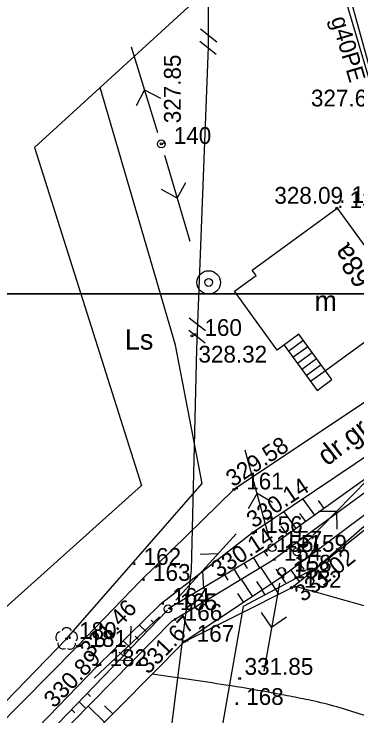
# Model space of a CAD drawing. Extents: x 4632591 to 4653165, y 5351032 to 5369868.
# Drawn here: x 4644663.8 to 4644694.4, y 5358462.3 to 5358525 of the extents above; entities that cross this region are included whole.
import ezdxf

# ---------------------------------------------------------------- set-up
doc = ezdxf.new("R2010")
doc.units = 0
for name, color, linetype in [('EADPD_238', 7, 'Continuous'), ('EBTPO_352', 7, 'Continuous'), ('EBUPP_312', 7, 'Continuous'), ('EDZPX_299', 7, 'Continuous'), ('EKLPK_217', 7, 'Continuous'), ('EUZPU_424', 7, 'Continuous'), ('SZZPZ_922', 7, 'Continuous'), ('UEEPA_510', 7, 'Continuous'), ('UEETA_516', 7, 'Continuous'), ('UGGPO_553', 7, 'Continuous'), ('UTTTA_521', 7, 'Continuous'), ('UWWPA_907', 7, 'Continuous'), ('Warstwa 40', 7, 'Continuous'), ('Warstwa 60', 7, 'Continuous'), ('Warstwa 62', 7, 'Continuous'), ('WUKPS_403', 7, 'Continuous'), ('WUKPS_820', 7, 'Continuous'), ('WUKPS_823', 7, 'Continuous'), ('WUKPS_824', 7, 'Continuous'), ('WWRPH_811', 7, 'Continuous')]:
    doc.layers.add(name, color=color, linetype=linetype)

msp = doc.modelspace()

# ---------------------------------------------------------------- linework, layer by layer
at = {"layer": 'EBTPO_352'}
for p, q in [((4644688.332, 5358494.893), (4644689.655, 5358495.855)), ((4644688.727, 5358494.350000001), (4644690.05, 5358495.312)), ((4644689.122, 5358493.807), (4644690.445, 5358494.769)), ((4644689.517, 5358493.264), (4644690.84, 5358494.226)), ((4644689.9120000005, 5358492.721), (4644691.235, 5358493.683)), ((4644691.63, 5358493.14), (4644690.307, 5358492.178))]:
    msp.add_line(p, q, dxfattribs=at)
msp.add_lwpolyline([(4644687.937, 5358495.437), (4644690.883, 5358491.386), (4644692.206, 5358492.348), (4644691.63, 5358493.14)], dxfattribs=at)
at = {"layer": 'EBUPP_312'}
msp.add_lwpolyline([(4644689.26, 5358496.399), (4644687.319, 5358494.987), (4644683.495, 5358500.243), (4644685.436, 5358501.655), (4644685.083, 5358502.14), (4644692.68, 5358507.67), (4644699.232, 5358498.669), (4644691.63, 5358493.14)], close=True, dxfattribs=at)
at = {"layer": 'EDZPX_299'}
for p, q in [((4644681.918138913, 5358522.506503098), (4644680.461517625, 5358523.663332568)), ((4644681.875868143, 5358521.407315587), (4644680.419246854, 5358522.5641450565)), ((4644680.9253407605, 5358496.690287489), (4644679.468719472, 5358497.847116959)), ((4644680.88306999, 5358495.591099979), (4644679.426448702, 5358496.747929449))]:
    msp.add_line(p, q, dxfattribs=at)
at = {"layer": 'EKLPK_217'}
msp.add_lwpolyline([(4644589.437877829, 5358446.057148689), (4644590.15, 5358443.3), (4644594.36, 5358439.41), (4644607.9, 5358437.69), (4644615.73, 5358442.350000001), (4644623.29, 5358443.5), (4644627.91, 5358442.78), (4644641.76, 5358446.850000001), (4644656.67, 5358456.98), (4644668.51, 5358469.17), (4644674.28, 5358475.79), (4644680.614947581, 5358483.058172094), (4644678.245093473, 5358495.410952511), (4644671.512576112, 5358518.445863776)], dxfattribs=at)
at = {"layer": 'EUZPU_424'}
for points in [[(4644736.519549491, 5358573.425323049), (4644734.7336056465, 5358569.580341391), (4644733.014156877, 5358558.486645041), (4644724.43, 5358530.37), (4644718.67, 5358515.99), (4644711.55, 5358501.11), (4644708.07, 5358496.17), (4644703.46, 5358490.97), (4644685.13, 5358478.64), (4644676.84, 5358472.22), (4644671.23, 5358466.74), (4644658.94, 5358454.03), (4644646.98, 5358446.3100000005), (4644643, 5358444.41)], [(4644729.51, 5358555.12), (4644722.11, 5358531.42), (4644716.49, 5358516.97), (4644709.43, 5358502.48), (4644706.3100000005, 5358497.61), (4644701.62, 5358493.26), (4644695.2079700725, 5358490.354165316), (4644683.44, 5358482.53), (4644675.12, 5358474.36), (4644669.43, 5358468.46), (4644657.26, 5358456.17), (4644645.62, 5358448.34)]]:
    msp.add_lwpolyline(points, dxfattribs=at)
at = {"layer": 'SZZPZ_922'}
msp.add_circle((4644668.51, 5358469.17), 0.09, dxfattribs=at)
for centre, start, end in [((4644668.517, 5358469.67), 30.769569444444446, 149.23063055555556), ((4644668.041, 5358469.322), 103.05194166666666, 221.33515277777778), ((4644668.992000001, 5358469.3270000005), 318.9390055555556, 77.55512500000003), ((4644668.218, 5358468.769), 174.17266944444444, 292.6156638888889), ((4644668.806, 5358468.762), 246.13102500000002, 4.522500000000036)]:
    msp.add_arc(centre, 0.5, start, end, dxfattribs=at)
at = {"layer": 'UEEPA_510'}
for centre in [(4644676.97, 5358513.41), (4644686.87, 5358477.32), (4644689.09, 5358476.96), (4644687.72, 5358475.19), (4644677.569690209, 5358471.853793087)]:
    msp.add_circle(centre, 0.35000000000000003, dxfattribs=at)
at = {"layer": 'UEETA_516'}
for p, q in [((4644676.659732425, 5358514.413112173), (4644674.295788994, 5358522.055871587)), ((4644675.47776071, 5358518.234491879), (4644674.7314681, 5358516.819794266)), ((4644675.47776071, 5358518.234491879), (4644676.892458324, 5358517.48819927)), ((4644677.26731119, 5358512.402971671), (4644679.53253931, 5358504.730374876)), ((4644678.399925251, 5358508.566673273), (4644679.164391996, 5358509.97163327)), ((4644678.399925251, 5358508.566673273), (4644676.994965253, 5358509.331140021)), ((4644686.588960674, 5358478.331690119), (4644684.447708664, 5358486.039805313)), ((4644689.82446119, 5358477.710377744), (4644695.420355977, 5358483.427541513)), ((4644685.518334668, 5358482.185747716), (4644684.7313193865, 5358480.793293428)), ((4644685.518334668, 5358482.185747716), (4644686.910788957, 5358481.398732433)), ((4644692.622408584, 5358480.568959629), (4644691.02302493, 5358480.551815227)), ((4644692.622408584, 5358480.568959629), (4644692.639552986, 5358478.969575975)), ((4644687.534542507, 5358474.156508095), (4644686.121533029, 5358466.282284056)), ((4644686.828037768, 5358470.219396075), (4644685.914583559, 5358471.532378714)), ((4644686.828037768, 5358470.219396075), (4644688.141020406, 5358471.132850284))]:
    msp.add_line(p, q, dxfattribs=at)
at = {"layer": 'UGGPO_553'}
for points in [[(4644690.36324522, 5358535.7036739), (4644691.579033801, 5358532.559831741), (4644696.43465227, 5358516.11393335), (4644701.2098301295, 5358500.333543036)], [(4644681.162880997, 5358527.280149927), (4644681.159171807, 5358525.742968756), (4644681.150276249, 5358522.056427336), (4644680.112786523, 5358495.078074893), (4644679.631088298, 5358475.317567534), (4644676.611747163, 5358451.335490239), (4644670.676629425, 5358406.387172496), (4644669.873103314, 5358402.059333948), (4644670.020547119, 5358384.82023951), (4644670.096309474, 5358376.259599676)], [(4644705.94, 5358488.66), (4644690.957985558, 5358475.612118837), (4644684.27689028, 5358472.067235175), (4644671.392685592, 5358398.424114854), (4644670.037926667, 5358391.220697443), (4644669.590232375, 5358385.605825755), (4644670.719480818, 5358377.844620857), (4644670.408710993, 5358376.132050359)]]:
    msp.add_lwpolyline(points, dxfattribs=at)
at = {"layer": 'UTTTA_521'}
for p, q in [((4644678.274844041, 5358472.631776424), (4644683.647444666, 5358478.559268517)), ((4644682.035664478, 5358476.781020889), (4644680.438113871, 5358476.7025731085)), ((4644680.6461756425, 5358475.248023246), (4644680.724623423, 5358473.650472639)), ((4644676.804508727, 5358471.134767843), (4644670.974554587, 5358465.656480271)), ((4644674.231312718, 5358468.716788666), (4644674.28102958, 5358470.315491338)), ((4644672.7235408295, 5358467.299966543), (4644674.322243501, 5358467.250249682))]:
    msp.add_line(p, q, dxfattribs=at)
at = {"layer": 'UWWPA_907'}
for radius in [1.05, 0.35000000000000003]:
    msp.add_circle((4644681.199047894, 5358501.026008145), radius, dxfattribs=at)
at = {"layer": 'Warstwa 40'}
msp.add_lwpolyline([(4644810.829869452, 5358555.0318941), (4644734.3245207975, 5358627.5855483), (4644688.903956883, 5358576.341480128), (4644696.208771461, 5358541.053777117), (4644665.649831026, 5358513.078865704), (4644675.210413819, 5358482.874703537), (4644634.264162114, 5358446.154900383), (4644624.659923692, 5358448.078175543), (4644610.340877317, 5358444.40646842), (4644593.08287162, 5358445.769308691), (4644584.820738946, 5358446.421757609), (4644558.950406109, 5358331.354730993), (4644690.288366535, 5358293.195203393), (4644705.733104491, 5358386.519320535), (4644692.287170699, 5358404.571880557), (4644776.589601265, 5358522.671629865)], close=True, dxfattribs=at)
at = {"layer": 'Warstwa 60'}
for points in [[(4644000, 5358500), (4644000, 5359000), (4644800, 5359000), (4644800, 5358500)], [(4644000, 5358000), (4644000, 5358500), (4644800, 5358500), (4644800, 5358000)]]:
    msp.add_lwpolyline(points, close=True, dxfattribs=at)
at = {"layer": 'WUKPS_403'}
for centre in [(4644676.97, 5358513.41), (4644692.6494402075, 5358507.655639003), (4644679.71, 5358496.25), (4644683.461336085, 5358482.520911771), (4644685.163998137, 5358478.658443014), (4644685.184781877, 5358478.635488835), (4644688.61, 5358473.75), (4644669.48148533, 5358468.51981774), (4644679.030445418, 5358468.92842047), (4644671.273675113, 5358466.782360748), (4644683.971323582, 5358465.642152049)]:
    msp.add_circle(centre, 0.09, dxfattribs=at)
at = {"layer": 'WUKPS_820'}
for p, q in [((4644690.67056977, 5358480.22442886), (4644689.63468914, 5358481.66988344)), ((4644691.52372413, 5358480.83563692), (4644691.0148026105, 5358481.54577532)), ((4644689.02520065, 5358479.04567047), (4644687.95450944, 5358480.53971538)), ((4644689.87835501, 5358479.656878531), (4644689.352036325, 5358480.39130076)), ((4644688.23298589, 5358478.47812013), (4644687.689254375, 5358479.23684806)), ((4644686.16107959, 5358476.99379771), (4644686.468647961, 5358476.56414307)), ((4644685.202212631, 5358476.41369715), (4644685.74191247, 5358475.5095691)), ((4644684.36842295, 5358475.91557166), (4644684.6395182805, 5358475.46142301)), ((4644686.83031895, 5358474.09258172), (4644685.84742375, 5358475.57334537)), ((4644689.32007011, 5358475.89314956), (4644689.690406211, 5358475.398476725)), ((4644682.63670593, 5358474.88100335), (4644682.910414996, 5358474.422479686)), ((4644683.47049561, 5358475.3791288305), (4644684.01538766, 5358474.46630978)), ((4644687.76009999, 5358474.72490132), (4644687.24333537, 5358475.414703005)), ((4644688.54007011, 5358475.30901049), (4644689.29744092, 5358474.2973672)), ((4644685.14331166, 5358472.97316566), (4644684.1130334, 5358474.52533762)), ((4644686.01805618, 5358473.55360362), (4644685.51519659, 5358474.3111838)), ((4644687.700070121, 5358474.67993764), (4644688.077492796, 5358474.175802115)), ((4644686.83028898, 5358474.09255175), (4644687.44695174, 5358473.16286366)), ((4644684.33104889, 5358472.43418757), (4644683.80451688, 5358473.2274431)), ((4644685.955544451, 5358473.5121138), (4644686.229349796, 5358473.099301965)), ((4644676.3681346, 5358470.55553343), (4644676.057976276, 5358470.854341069)), ((4644675.641429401, 5358469.801718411), (4644674.99847492, 5358470.42115739)), ((4644674.96663172, 5358469.10174731), (4644674.634643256, 5358469.421600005)), ((4644674.23992652, 5358468.34793229), (4644673.55330832, 5358469.0094647)), ((4644673.56512883, 5358467.64796119), (4644673.21130691, 5358467.98886214)), ((4644670.34690295, 5358464.30967751), (4644670.657701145, 5358464.009781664)), ((4644669.620197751, 5358463.55586248), (4644670.23380692, 5358462.96377077)), ((4644671.892592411, 5358461.72104227), (4644670.43383711, 5358463.16691037)), ((4644672.63174135, 5358462.46657418), (4644671.90109096, 5358463.190770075)), ((4644668.94540007, 5358462.85589139), (4644669.24849646, 5358462.56342037))]:
    msp.add_line(p, q, dxfattribs=at)
at = {"layer": 'WUKPS_823'}
for points in [[(4644712.58, 5358510.48), (4644705.93, 5358498.47), (4644703.61, 5358500.11), (4644701.95, 5358502.17), (4644698.600000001, 5358509.3100000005), (4644696.04, 5358518.57), (4644693.54, 5358527.62), (4644691.116713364, 5358536.392297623)], [(4644719.600000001, 5358515.83), (4644712.25, 5358500.45), (4644704.26, 5358489.96), (4644686.100000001, 5358476.95), (4644677.569690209, 5358471.853793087)], [(4644721.2, 5358515.13), (4644714.12, 5358499.12), (4644705.7, 5358488.16), (4644687.58, 5358474.59), (4644679.0200000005, 5358468.91)], [(4644677.51, 5358471.74), (4644659.55, 5358453.11), (4644654.2, 5358447.600000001), (4644648.5200000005, 5358444.01), (4644643.29, 5358441.850000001), (4644629.93, 5358437.54), (4644615.41, 5358433.87)], [(4644639.94, 5358420.42), (4644623.03, 5358430.09), (4644638.84, 5358436.33), (4644647.86, 5358440.19), (4644656.49, 5358446.28), (4644661.65, 5358451.39), (4644679.0200000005, 5358468.91)]]:
    msp.add_lwpolyline(points, dxfattribs=at)
at = {"layer": 'WUKPS_824'}
for points in [[(4644677.95, 5358470.8), (4644686.8, 5358476.15), (4644704.84, 5358489.38), (4644712.86, 5358500.03), (4644720.44, 5358515.5)], [(4644679.0200000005, 5358468.91), (4644688.61, 5358473.75), (4644706.29, 5358487.8), (4644715.76, 5358498.0600000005), (4644722.2, 5358514.32)], [(4644677.95, 5358470.8), (4644659.95, 5358452.5200000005), (4644654.91, 5358447.2), (4644647.16, 5358440.97), (4644638.59, 5358437.48), (4644621.75, 5358431.0200000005), (4644620.7871284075, 5358430.650632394)]]:
    msp.add_lwpolyline(points, dxfattribs=at)
at = {"layer": 'WWRPH_811'}
for points in [[(4644688.820823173, 5358473.917537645), (4644702.411381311, 5358470.412671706), (4644714.708434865, 5358468.482234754)], [(4644710.617979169, 5358459.182324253), (4644707.834562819, 5358459.5590160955), (4644705.059895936, 5358460.014690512), (4644702.293301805, 5358460.53340285), (4644699.534103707, 5358461.099208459), (4644697.221999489, 5358461.691022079), (4644694.942031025, 5358462.395614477), (4644692.6624634, 5358463.093708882), (4644690.351561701, 5358463.6660285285), (4644688.455351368, 5358464.04246788), (4644686.556139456, 5358464.403653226), (4644682.743583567, 5358465.04162863), (4644676.146532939, 5358466.011718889)]]:
    msp.add_spline(points, degree=3, dxfattribs=at)

# ---------------------------------------------------------------- texts
at = {"layer": 'EADPD_238'}
msp.add_text('68a', height=1.8, rotation=124.59320622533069, dxfattribs=at).set_placement((4644695.926350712, 5358501.379996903))
at = {"layer": 'EBUPP_312'}
msp.add_text('m', height=1.8, dxfattribs=at).set_placement((4644690.651668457, 5358498.479138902))
at = {"layer": 'EKLPK_217'}
msp.add_text('Ls', height=1.8, dxfattribs=at).set_placement((4644673.718354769, 5358495.02772661))
at = {"layer": 'EUZPU_424'}
msp.add_text('dr.gr.', height=1.8, rotation=37.75516831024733, dxfattribs=at).set_placement((4644691.788202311, 5358484.5635582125))
at = {"layer": 'UGGPO_553'}
msp.add_text('g40PE', height=1.5, rotation=286.4449791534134, dxfattribs=at).set_placement((4644692.106094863, 5358524.578055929))
at = {"layer": 'Warstwa 62'}
for s, p in [('. 140', (4644676.97, 5358513.41)), ('. 136', (4644692.86, 5358508.13)), ('. 135', (4644692.68, 5358507.67)), ('. 160', (4644679.71, 5358496.25)), ('. 161', (4644683.44, 5358482.53)), ('. 156', (4644685.13, 5358478.64)), ('. 157', (4644686.87, 5358477.32)), ('. 155', (4644686.100000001, 5358476.95)), ('. 159', (4644689.09, 5358476.96)), ('. 154', (4644686.8, 5358476.15)), ('. 162', (4644674.28, 5358475.79)), ('. 158', (4644687.72, 5358475.19)), ('. 163', (4644675.12, 5358474.36)), ('. 153', (4644687.58, 5358474.59)), ('. 152', (4644688.61, 5358473.75)), ('. 164', (4644676.84, 5358472.22)), ('. 165', (4644677.51, 5358471.74)), ('. 166', (4644677.95, 5358470.8)), ('. 180', (4644668.51, 5358469.17)), ('. 181', (4644669.43, 5358468.46)), ('. 167', (4644679.0200000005, 5358468.91)), ('. 182', (4644671.23, 5358466.74)), ('. 168', (4644683.44, 5358463.2700000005))]:
    msp.add_text(s, height=1.5, dxfattribs=at).set_placement(p)
at = {"layer": 'WUKPS_403'}
for s, rotation, p in [('327.85', 90, (4644678.710146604, 5358515.25710287)), ('329.58', 33.618724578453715, (4644683.3812108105, 5358482.701421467)), ('330.14', 33.92744981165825, (4644685.224844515, 5358479.01656486)), ('330.14', 33.618724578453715, (4644682.059143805, 5358474.586946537)), ('331.02', 38.47357781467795, (4644689.636884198, 5358472.412100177)), ('331.46', 46.038032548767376, (4644670.632672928, 5358467.393371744)), ('331.67', 46.038032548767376, (4644675.798964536, 5358465.945712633)), ('330.89', 46.038032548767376, (4644667.397615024, 5358462.924324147))]:
    msp.add_text(s, height=1.5, rotation=rotation, dxfattribs=at).set_placement(p)
for s, p in [('327.65', (4644690.338952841, 5358516.756022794)), ('328.09', (4644687.068214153, 5358508.06053228)), ('328.32', (4644680.288238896, 5358493.86419681)), ('331.85', (4644684.4120125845, 5358465.963058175))]:
    msp.add_text(s, height=1.5, dxfattribs=at).set_placement(p)

doc.saveas('drawing.dxf')
